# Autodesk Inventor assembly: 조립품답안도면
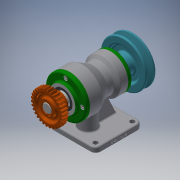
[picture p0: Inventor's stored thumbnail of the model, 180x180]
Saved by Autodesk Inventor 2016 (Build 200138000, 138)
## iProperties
Created: 2019-01
Part Number: 조립품답안도면
Material: 일반
Document SubType Name: Weldment
Designer: 605-12
Weld Material: Welded Aluminum-6061
Author: 605-12
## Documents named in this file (15)
- C:\Users\605-12\Desktop\490107V1033\조립품답안도면.iam
- C:\Users\605-12\Desktop\490107V1033\본체.ipt
- C:\Users\605-12\Desktop\490107V1033\베어링 6205.ipt
- C:\Users\605-12\Desktop\490107V1033\앞커버.ipt
- C:\Users\605-12\Desktop\490107V1033\오일 실 25 38 8.ipt
- C:\Users\605-12\Desktop\490107V1033\뒤커버.ipt
- C:\Users\605-12\Desktop\490107V1033\베어링 6203.ipt
- C:\Users\605-12\Desktop\490107V1033\오일 실 17 30 8.ipt
- C:\Users\605-12\Desktop\490107V1033\볼트 M4.ipt
- C:\Users\605-12\Desktop\490107V1033\축.ipt
- C:\Users\605-12\Desktop\490107V1033\키 5 x 5 x 20.ipt
- C:\Users\605-12\Desktop\490107V1033\키 6 x 6 x 18.ipt
- C:\Users\605-12\Desktop\490107V1033\V-벨트풀리.ipt
- C:\Users\605-12\Desktop\490107V1033\스퍼기어.ipt
- C:\Users\605-12\Desktop\490107V1033\멈춤나사 M3.ipt
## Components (1 placed, 1 different names)
1. V-벨트풀리:1 — 플러쉬:2
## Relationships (1: Flush 1)
- 플러쉬:2 [Flush]: V-벨트풀리:1
